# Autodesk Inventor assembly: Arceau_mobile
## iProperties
Created: 2011-01
Part Number: Arceau_mobile
Document SubType Name: Assembly
Designer: eric
Mass: 693.402 g
Surface Area: 6001.03 cm^2
Volume: 693.402 cm^3
Density: 1 g/cm^3
Norme de conversion: IGES 5.3
Nom du fichier: No Iges File Name specified
Préprocesseur: Autodesk Inventor 2011
Postprocesseur: Build: 342, Release: 2008 SP3 - Date: Tue 05/27/2008
Unités envoyées: MM
Incertitude: 0.01
Author: eric
